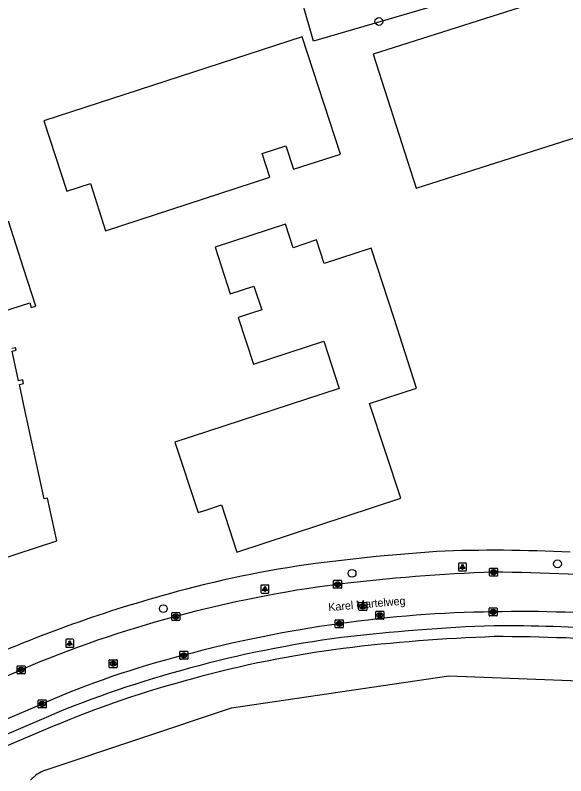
# Model space of a CAD drawing. Extents: x 159503 to 160347, y 382525 to 383272.
# Drawn here: x 159637.5 to 159706.3, y 382704.5 to 382799.5 of the extents above; entities that cross this region are included whole.
import ezdxf

# ---------------------------------------------------------------- set-up
doc = ezdxf.new("R2010")
doc.units = 0
for name, color, linetype in [('IMGEO_Boom', 7, 'Continuous'), ('IMGEO_Groenvoorziening', 7, 'Continuous'), ('IMGEO_Kolk', 7, 'Continuous'), ('IMGEO_Lichtpunt', 7, 'Continuous'), ('IMGEO_Openbare_ruimte_label', 7, 'Continuous'), ('IMGEO_Pand', 7, 'Continuous'), ('IMGEO_Rijbaan_lokaal_open', 7, 'Continuous'), ('IMGEO_Rioolput', 7, 'Continuous'), ('IMGEO_Voetpad_open', 7, 'Continuous')]:
    doc.layers.add(name, color=color, linetype=linetype)

msp = doc.modelspace()

# ---------------------------------------------------------------- linework, layer by layer
at = {"layer": 'IMGEO_Boom'}
for centre in [(159682.989, 382798.739), (159705.309, 382730.985), (159679.639, 382729.808), (159656.051, 382725.396)]:
    msp.add_circle(centre, 0.489, dxfattribs=at)
at = {"layer": 'IMGEO_Groenvoorziening'}
msp.add_lwpolyline([(159742.845, 382815.409), (159730.6, 382811.547), (159707.693, 382805.912), (159674.81, 382796.272), (159673.434, 382801.05)], dxfattribs=at)
at = {"layer": 'IMGEO_Kolk'}
for p, q in [((159696.822, 382729.522), (159696.822, 382730.374)), ((159696.897, 382730.448), (159697.749, 382730.448)), ((159697.823, 382730.374), (159697.823, 382729.522)), ((159697.749, 382729.448), (159696.897, 382729.448)), ((159697.333, 382729.668), (159697.308, 382729.668)), ((159697.31, 382730.228), (159697.335, 382730.228)), ((159677.332, 382728.004), (159677.332, 382728.856)), ((159677.407, 382728.93), (159678.259, 382728.93)), ((159677.82, 382728.71), (159677.845, 382728.71)), ((159678.333, 382728.856), (159678.333, 382728.004)), ((159678.259, 382727.93), (159677.407, 382727.93)), ((159677.843, 382728.15), (159677.818, 382728.15)), ((159657.109, 382723.984), (159657.109, 382724.836)), ((159657.184, 382724.91), (159658.036, 382724.91)), ((159657.597, 382724.69), (159657.622, 382724.69)), ((159658.11, 382724.836), (159658.11, 382723.984)), ((159696.763, 382724.564), (159696.763, 382725.416)), ((159696.838, 382725.49), (159697.69, 382725.49)), ((159697.274, 382724.71), (159697.249, 382724.71)), ((159697.251, 382725.27), (159697.276, 382725.27)), ((159697.764, 382725.416), (159697.764, 382724.564)), ((159658.036, 382723.91), (159657.184, 382723.91)), ((159657.62, 382724.13), (159657.595, 382724.13)), ((159677.544, 382723.076), (159677.544, 382723.928)), ((159677.619, 382724.002), (159678.471, 382724.002)), ((159678.032, 382723.782), (159678.057, 382723.782)), ((159678.545, 382723.928), (159678.545, 382723.076)), ((159697.69, 382724.49), (159696.838, 382724.49)), ((159678.471, 382723.002), (159677.619, 382723.002)), ((159678.055, 382723.222), (159678.03, 382723.222)), ((159658.106, 382719.138), (159658.106, 382719.99)), ((159658.181, 382720.064), (159659.033, 382720.064)), ((159658.594, 382719.844), (159658.619, 382719.844)), ((159659.107, 382719.99), (159659.107, 382719.138)), ((159659.033, 382719.064), (159658.181, 382719.064)), ((159658.617, 382719.284), (159658.592, 382719.284)), ((159637.776, 382717.316), (159637.776, 382718.168)), ((159637.851, 382718.242), (159638.703, 382718.242)), ((159638.264, 382718.022), (159638.289, 382718.022)), ((159638.777, 382718.168), (159638.777, 382717.316)), ((159638.703, 382717.242), (159637.851, 382717.242)), ((159638.287, 382717.462), (159638.262, 382717.462)), ((159640.425, 382713.063), (159640.425, 382713.915)), ((159640.5, 382713.989), (159641.352, 382713.989)), ((159640.936, 382713.209), (159640.911, 382713.209)), ((159640.913, 382713.769), (159640.938, 382713.769)), ((159641.426, 382713.915), (159641.426, 382713.063)), ((159641.352, 382712.989), (159640.5, 382712.989))]:
    msp.add_line(p, q, dxfattribs=at)
for points in [[(159696.822, 382729.522), (159696.822, 382730.374)], [(159696.897, 382730.448), (159697.749, 382730.448)], [(159697.823, 382730.374), (159697.823, 382729.522)], [(159697.749, 382729.448), (159696.897, 382729.448)], [(159697.143, 382730.148), (159697.266, 382730.148), (159697.266, 382729.997), (159697.396, 382730.148), (159697.56, 382730.148), (159697.414, 382729.997), (159697.567, 382729.748), (159697.415, 382729.748), (159697.33, 382729.912), (159697.266, 382729.845), (159697.266, 382729.748), (159697.143, 382729.748), (159697.143, 382730.148)], [(159677.332, 382728.004), (159677.332, 382728.856)], [(159677.407, 382728.93), (159678.259, 382728.93)], [(159677.653, 382728.63), (159677.776, 382728.63), (159677.776, 382728.479), (159677.906, 382728.63), (159678.07, 382728.63), (159677.924, 382728.479), (159678.077, 382728.23), (159677.925, 382728.23), (159677.84, 382728.394), (159677.776, 382728.327), (159677.776, 382728.23), (159677.653, 382728.23), (159677.653, 382728.63)], [(159678.333, 382728.856), (159678.333, 382728.004)], [(159678.259, 382727.93), (159677.407, 382727.93)], [(159657.109, 382723.984), (159657.109, 382724.836)], [(159657.184, 382724.91), (159658.036, 382724.91)], [(159657.43, 382724.61), (159657.553, 382724.61), (159657.553, 382724.459), (159657.683, 382724.61), (159657.847, 382724.61), (159657.701, 382724.459), (159657.854, 382724.21), (159657.702, 382724.21), (159657.617, 382724.374), (159657.553, 382724.307), (159657.553, 382724.21), (159657.43, 382724.21), (159657.43, 382724.61)], [(159658.11, 382724.836), (159658.11, 382723.984)], [(159696.763, 382724.564), (159696.763, 382725.416)], [(159696.838, 382725.49), (159697.69, 382725.49)], [(159697.084, 382725.19), (159697.207, 382725.19), (159697.207, 382725.039), (159697.337, 382725.19), (159697.501, 382725.19), (159697.355, 382725.039), (159697.508, 382724.79), (159697.356, 382724.79), (159697.271, 382724.954), (159697.207, 382724.887), (159697.207, 382724.79), (159697.084, 382724.79), (159697.084, 382725.19)], [(159697.764, 382725.416), (159697.764, 382724.564)], [(159658.036, 382723.91), (159657.184, 382723.91)], [(159677.544, 382723.076), (159677.544, 382723.928)], [(159677.619, 382724.002), (159678.471, 382724.002)], [(159677.865, 382723.702), (159677.988, 382723.702), (159677.988, 382723.551), (159678.118, 382723.702), (159678.282, 382723.702), (159678.136, 382723.551), (159678.289, 382723.302), (159678.137, 382723.302), (159678.052, 382723.466), (159677.988, 382723.399), (159677.988, 382723.302), (159677.865, 382723.302), (159677.865, 382723.702)], [(159678.545, 382723.928), (159678.545, 382723.076)], [(159697.69, 382724.49), (159696.838, 382724.49)], [(159678.471, 382723.002), (159677.619, 382723.002)], [(159658.106, 382719.138), (159658.106, 382719.99)], [(159658.181, 382720.064), (159659.033, 382720.064)], [(159659.107, 382719.99), (159659.107, 382719.138)], [(159659.033, 382719.064), (159658.181, 382719.064)], [(159658.427, 382719.764), (159658.55, 382719.764), (159658.55, 382719.613), (159658.68, 382719.764), (159658.844, 382719.764), (159658.698, 382719.613), (159658.851, 382719.364), (159658.699, 382719.364), (159658.614, 382719.528), (159658.55, 382719.461), (159658.55, 382719.364), (159658.427, 382719.364), (159658.427, 382719.764)], [(159637.776, 382717.316), (159637.776, 382718.168)], [(159637.851, 382718.242), (159638.703, 382718.242)], [(159638.097, 382717.942), (159638.22, 382717.942), (159638.22, 382717.791), (159638.35, 382717.942), (159638.514, 382717.942), (159638.368, 382717.791), (159638.521, 382717.542), (159638.369, 382717.542), (159638.284, 382717.706), (159638.22, 382717.639), (159638.22, 382717.542), (159638.097, 382717.542), (159638.097, 382717.942)], [(159638.777, 382718.168), (159638.777, 382717.316)], [(159638.703, 382717.242), (159637.851, 382717.242)], [(159640.425, 382713.063), (159640.425, 382713.915)], [(159640.5, 382713.989), (159641.352, 382713.989)], [(159640.746, 382713.689), (159640.869, 382713.689), (159640.869, 382713.538), (159640.999, 382713.689), (159641.163, 382713.689), (159641.017, 382713.538), (159641.17, 382713.289), (159641.018, 382713.289), (159640.933, 382713.453), (159640.869, 382713.386), (159640.869, 382713.289), (159640.746, 382713.289), (159640.746, 382713.689)], [(159641.426, 382713.915), (159641.426, 382713.063)], [(159641.352, 382712.989), (159640.5, 382712.989)]]:
    msp.add_lwpolyline(points, dxfattribs=at)
for centre, start, end in [((159696.899, 382730.372), 91.55205, 178.44795), ((159696.899, 382730.372), 91.55205, 178.44795), ((159697.747, 382730.372), 1.55205, 88.44795), ((159697.747, 382730.372), 1.55205, 88.44795), ((159696.899, 382729.524), 181.55205, 268.44795), ((159696.899, 382729.524), 181.55205, 268.44795), ((159697.747, 382729.524), 271.55205, 358.44795), ((159697.747, 382729.524), 271.55205, 358.44795), ((159677.409, 382728.854), 91.55205, 178.44795), ((159677.409, 382728.854), 91.55205, 178.44795), ((159678.257, 382728.854), 1.55205, 88.44795), ((159678.257, 382728.854), 1.55205, 88.44795), ((159677.409, 382728.006), 181.55205, 268.44795), ((159677.409, 382728.006), 181.55205, 268.44795), ((159678.257, 382728.006), 271.55205, 358.44795), ((159678.257, 382728.006), 271.55205, 358.44795), ((159657.186, 382724.834), 91.55205, 178.44795), ((159657.186, 382724.834), 91.55205, 178.44795), ((159658.034, 382724.834), 1.55205, 88.44795), ((159658.034, 382724.834), 1.55205, 88.44795), ((159696.84, 382725.414), 91.55205, 178.44795), ((159696.84, 382725.414), 91.55205, 178.44795), ((159696.84, 382724.566), 181.55205, 268.44795), ((159696.84, 382724.566), 181.55205, 268.44795), ((159697.688, 382725.414), 1.55205, 88.44795), ((159697.688, 382725.414), 1.55205, 88.44795), ((159697.688, 382724.566), 271.55205, 358.44795), ((159697.688, 382724.566), 271.55205, 358.44795), ((159657.186, 382723.986), 181.55205, 268.44795), ((159657.186, 382723.986), 181.55205, 268.44795), ((159658.034, 382723.986), 271.55205, 358.44795), ((159658.034, 382723.986), 271.55205, 358.44795), ((159677.621, 382723.926), 91.55205, 178.44795), ((159677.621, 382723.926), 91.55205, 178.44795), ((159678.469, 382723.926), 1.55205, 88.44795), ((159678.469, 382723.926), 1.55205, 88.44795), ((159677.621, 382723.078), 181.55205, 268.44795), ((159677.621, 382723.078), 181.55205, 268.44795), ((159678.469, 382723.078), 271.55205, 358.44795), ((159678.469, 382723.078), 271.55205, 358.44795), ((159658.183, 382719.988), 91.55205, 178.44795), ((159658.183, 382719.988), 91.55205, 178.44795), ((159659.031, 382719.988), 1.55205, 88.44795), ((159659.031, 382719.988), 1.55205, 88.44795), ((159658.183, 382719.14), 181.55205, 268.44795), ((159658.183, 382719.14), 181.55205, 268.44795), ((159659.031, 382719.14), 271.55205, 358.44795), ((159659.031, 382719.14), 271.55205, 358.44795), ((159637.853, 382718.166), 91.55205, 178.44795), ((159637.853, 382718.166), 91.55205, 178.44795), ((159638.701, 382718.166), 1.55205, 88.44795), ((159638.701, 382718.166), 1.55205, 88.44795), ((159637.853, 382717.318), 181.55205, 268.44795), ((159637.853, 382717.318), 181.55205, 268.44795), ((159638.701, 382717.318), 271.55205, 358.44795), ((159638.701, 382717.318), 271.55205, 358.44795), ((159640.502, 382713.913), 91.55205, 178.44795), ((159640.502, 382713.913), 91.55205, 178.44795), ((159641.35, 382713.913), 1.55205, 88.44795), ((159641.35, 382713.913), 1.55205, 88.44795), ((159640.502, 382713.065), 181.55205, 268.44795), ((159640.502, 382713.065), 181.55205, 268.44795), ((159641.35, 382713.065), 271.55205, 358.44795), ((159641.35, 382713.065), 271.55205, 358.44795)]:
    msp.add_arc(centre, 0.0765, start, end, dxfattribs=at)
for centre, major_axis, ratio, start_param, end_param in [((159697.309, 382729.948), (-0.387, 0.002), 0.722429, 4.712389, 7.853982), ((159697.334, 382729.948), (-0.39, 0.002), 0.717154, 1.570796, 4.712389), ((159677.819, 382728.43), (-0.387, 0.002), 0.722429, 4.712389, 7.853982), ((159677.844, 382728.43), (-0.39, 0.002), 0.717154, 1.570796, 4.712389), ((159657.596, 382724.41), (-0.387, 0.002), 0.722429, 4.712389, 7.853982), ((159657.621, 382724.41), (-0.39, 0.002), 0.717154, 1.570796, 4.712389), ((159697.25, 382724.99), (-0.387, 0.002), 0.722429, 4.712389, 7.853982), ((159697.275, 382724.99), (-0.39, 0.002), 0.717154, 1.570796, 4.712389), ((159678.031, 382723.502), (-0.387, 0.002), 0.722429, 4.712389, 7.853982), ((159678.056, 382723.502), (-0.39, 0.002), 0.717154, 1.570796, 4.712389), ((159658.593, 382719.564), (-0.387, 0.002), 0.722429, 4.712389, 7.853982), ((159658.618, 382719.564), (-0.39, 0.002), 0.717154, 1.570796, 4.712389), ((159638.263, 382717.742), (-0.387, 0.002), 0.722429, 4.712389, 7.853982), ((159638.288, 382717.742), (-0.39, 0.002), 0.717154, 1.570796, 4.712389), ((159640.912, 382713.489), (-0.387, 0.002), 0.722429, 4.712389, 7.853982), ((159640.937, 382713.489), (-0.39, 0.002), 0.717154, 1.570796, 4.712389)]:
    msp.add_ellipse(centre, major_axis=major_axis, ratio=ratio, start_param=start_param, end_param=end_param, dxfattribs=at)
at = {"layer": 'IMGEO_Lichtpunt'}
for p, q in [((159692.934, 382730.998), (159692.934, 382730.191)), ((159692.934, 382730.998), (159692.934, 382730.191)), ((159693.836, 382731.093), (159693.028, 382731.093)), ((159693.836, 382731.093), (159693.028, 382731.093)), ((159693.93, 382730.191), (159693.93, 382730.998)), ((159693.93, 382730.191), (159693.93, 382730.998)), ((159693.028, 382730.097), (159693.836, 382730.097)), ((159693.028, 382730.097), (159693.836, 382730.097)), ((159668.256, 382728.242), (159668.256, 382727.435)), ((159668.256, 382728.242), (159668.256, 382727.435)), ((159669.158, 382728.337), (159668.35, 382728.337)), ((159669.158, 382728.337), (159668.35, 382728.337)), ((159669.252, 382727.435), (159669.252, 382728.242)), ((159669.252, 382727.435), (159669.252, 382728.242)), ((159668.35, 382727.341), (159669.158, 382727.341)), ((159668.35, 382727.341), (159669.158, 382727.341)), ((159643.86, 382721.465), (159643.86, 382720.658)), ((159643.86, 382721.465), (159643.86, 382720.658)), ((159644.762, 382721.56), (159643.954, 382721.56)), ((159644.762, 382721.56), (159643.954, 382721.56)), ((159644.856, 382720.658), (159644.856, 382721.465)), ((159644.856, 382720.658), (159644.856, 382721.465)), ((159643.954, 382720.564), (159644.762, 382720.564)), ((159643.954, 382720.564), (159644.762, 382720.564))]:
    msp.add_line(p, q, dxfattribs=at)
for points in [[(159693.308, 382730.662), (159693.347, 382730.634), (159693.159, 382730.372), (159693.121, 382730.399), (159693.308, 382730.662)], [(159693.41, 382730.614), (159693.457, 382730.614), (159693.457, 382730.292), (159693.41, 382730.292), (159693.41, 382730.614)], [(159693.52, 382730.634), (159693.558, 382730.661), (159693.745, 382730.399), (159693.706, 382730.371), (159693.52, 382730.634)], [(159668.63, 382727.906), (159668.669, 382727.878), (159668.481, 382727.616), (159668.443, 382727.643), (159668.63, 382727.906)], [(159668.732, 382727.858), (159668.779, 382727.858), (159668.779, 382727.536), (159668.732, 382727.536), (159668.732, 382727.858)], [(159668.842, 382727.878), (159668.88, 382727.905), (159669.067, 382727.643), (159669.028, 382727.615), (159668.842, 382727.878)], [(159644.234, 382721.129), (159644.273, 382721.101), (159644.085, 382720.839), (159644.047, 382720.866), (159644.234, 382721.129)], [(159644.336, 382721.081), (159644.383, 382721.081), (159644.383, 382720.759), (159644.336, 382720.759), (159644.336, 382721.081)], [(159644.446, 382721.101), (159644.484, 382721.128), (159644.671, 382720.866), (159644.632, 382720.838), (159644.446, 382721.101)]]:
    msp.add_lwpolyline(points, dxfattribs=at)
for centre in [(159693.433, 382730.796), (159668.755, 382728.04), (159644.359, 382721.263)]:
    msp.add_circle(centre, 0.0994, dxfattribs=at)
for centre, start, end in [((159693.028, 382730.998), 90, 180), ((159693.028, 382730.998), 90, 180), ((159693.836, 382730.998), 0, 90), ((159693.836, 382730.998), 0, 90), ((159693.028, 382730.191), 180, 270), ((159693.028, 382730.191), 180, 270), ((159693.836, 382730.191), 270, 0), ((159693.836, 382730.191), 270, 360), ((159668.35, 382728.242), 90, 180), ((159668.35, 382728.242), 90, 180), ((159668.35, 382727.435), 180, 270), ((159668.35, 382727.435), 180, 270), ((159669.158, 382728.242), 0, 90), ((159669.158, 382728.242), 0, 90), ((159669.158, 382727.435), 270, 0), ((159669.158, 382727.435), 270, 360), ((159643.954, 382721.465), 90, 180), ((159643.954, 382721.465), 90, 180), ((159644.762, 382721.465), 0, 90), ((159644.762, 382721.465), 0, 90), ((159643.954, 382720.658), 180, 270), ((159643.954, 382720.658), 180, 270), ((159644.762, 382720.658), 270, 0), ((159644.762, 382720.658), 270, 360)]:
    msp.add_arc(centre, 0.0946, start, end, dxfattribs=at)
at = {"layer": 'IMGEO_Pand'}
for points in [[(159705.767, 382802.152), (159682.294, 382794.673), (159687.633, 382777.914), (159713.049, 382786.012), (159722.358, 382756.794), (159722.657, 382756.889), (159723.605, 382753.912), (159720.541, 382752.936), (159721.48, 382750), (159722.471, 382746.901), (159723.999, 382742.131), (159724.396, 382740.892), (159752.918, 382750), (159753.541, 382750.199), (159749.635, 382762.458), (159747.561, 382761.797), (159745.396, 382768.592), (159738.73, 382766.468), (159735.002, 382765.28), (159731.853, 382775.164), (159733.127, 382775.57), (159726.63, 382795.959)], [(159673.384, 382796.837), (159641.142, 382786.337), (159644.013, 382777.531), (159646.935, 382778.494), (159648.834, 382772.604), (159669.369, 382779.311), (159668.397, 382782.238), (159671.375, 382783.21), (159672.33, 382780.28), (159678.18, 382782.18), (159673.384, 382796.837)], [(159635.888, 382762.477), (159639.355, 382763.579), (159639.54, 382762.997), (159640.111, 382763.179), (159638.587, 382767.942), (159636.711, 382773.808)], [(159681.815, 382751.023), (159687.697, 382752.922), (159684.881, 382761.646), (159682.02, 382770.428), (159676.161, 382768.5), (159675.209, 382771.449), (159672.267, 382770.481), (159671.303, 382773.418), (159662.523, 382770.552), (159664.417, 382764.699), (159667.364, 382765.67), (159668.349, 382762.731), (159665.398, 382761.756), (159667.31, 382755.914), (159676.106, 382758.788), (159678.029, 382752.88), (159657.503, 382746.17), (159660.423, 382737.392), (159661.358, 382737.709), (159663.316, 382738.364), (159665.238, 382732.431), (159685.741, 382739.181), (159681.815, 382751.023)], [(159625.037, 382728.065), (159642.741, 382733.862), (159641.591, 382739.183), (159641.168, 382739.092), (159638.804, 382750), (159638.069, 382753.392), (159638.582, 382753.503), (159638.48, 382753.973), (159637.963, 382753.86), (159637.162, 382757.556), (159637.668, 382757.666), (159637.599, 382757.984), (159637.108, 382757.877)], [(159641.27, 382705.207), (159664.57, 382713.021), (159691.74, 382716.986), (159715.697, 382716.063)]]:
    msp.add_lwpolyline(points, dxfattribs=at)
msp.add_arc((159642.683, 382701.29), 4.164, 109.83892, 140.35503, dxfattribs=at)
at = {"layer": 'IMGEO_Rijbaan_lokaal_open'}
for points in [[(159623.68, 382711.468), (159624.794, 382711.953), (159638.277, 382717.741)], [(159624.664, 382706.553), (159626.254, 382707.24), (159640.926, 382713.49)]]:
    msp.add_lwpolyline(points, dxfattribs=at)
for centre, radius, start, end in [((159705.491, 382499.343), 230.749, 92.02869, 96.88426), ((159693.353, 382379.227), 350.742, 86.30914, 89.35141), ((159697.26, 382577.785), 151.89, 97.34835, 105.132), ((159699.017, 382577.567), 147.434, 90.68145, 98.17842), ((159700.776, 382560.643), 164.385, 84.95233, 91.22406), ((159692.261, 382592.582), 136.305, 104.72718, 113.3317), ((159698.899, 382570.59), 154.328, 97.76654, 105.13436), ((159685.275, 382613.183), 109.673, 104.07275, 113.85158)]:
    msp.add_arc(centre, radius, start, end, dxfattribs=at)
at = {"layer": 'IMGEO_Rioolput'}
for p, q in [((159680.491, 382725.238), (159680.491, 382726.09)), ((159680.566, 382726.164), (159681.418, 382726.164)), ((159680.979, 382725.944), (159681.004, 382725.944)), ((159681.492, 382726.09), (159681.492, 382725.238)), ((159681.418, 382725.164), (159680.566, 382725.164)), ((159681.002, 382725.384), (159680.977, 382725.384)), ((159682.608, 382724.15), (159682.608, 382725.002)), ((159682.683, 382725.076), (159683.535, 382725.076)), ((159683.096, 382724.856), (159683.121, 382724.856)), ((159683.609, 382725.002), (159683.609, 382724.15)), ((159683.535, 382724.076), (159682.683, 382724.076)), ((159683.119, 382724.296), (159683.094, 382724.296)), ((159649.287, 382718.091), (159649.287, 382718.943)), ((159649.362, 382719.017), (159650.214, 382719.017)), ((159650.288, 382718.943), (159650.288, 382718.091)), ((159650.214, 382718.017), (159649.362, 382718.017)), ((159649.798, 382718.237), (159649.773, 382718.237)), ((159649.775, 382718.797), (159649.8, 382718.797))]:
    msp.add_line(p, q, dxfattribs=at)
for points in [[(159680.491, 382725.238), (159680.491, 382726.09)], [(159680.566, 382726.164), (159681.418, 382726.164)], [(159681.08, 382725.862), (159680.828, 382725.864), (159680.828, 382725.464)], [(159680.828, 382725.464), (159680.952, 382725.464), (159680.952, 382725.626), (159680.963, 382725.626)], [(159681.006, 382725.783), (159680.952, 382725.783), (159680.952, 382725.702)], [(159680.952, 382725.702), (159681.004, 382725.702)], [(159681.01, 382725.597), (159681.081, 382725.464), (159681.221, 382725.464), (159681.156, 382725.59)], [(159681.492, 382726.09), (159681.492, 382725.238)], [(159681.418, 382725.164), (159680.566, 382725.164)], [(159682.608, 382724.15), (159682.608, 382725.002)], [(159682.683, 382725.076), (159683.535, 382725.076)], [(159683.197, 382724.774), (159682.945, 382724.776), (159682.945, 382724.376)], [(159683.123, 382724.695), (159683.069, 382724.695), (159683.069, 382724.614)], [(159683.069, 382724.614), (159683.121, 382724.614)], [(159683.609, 382725.002), (159683.609, 382724.15)], [(159683.535, 382724.076), (159682.683, 382724.076)], [(159682.945, 382724.376), (159683.069, 382724.376), (159683.069, 382724.538), (159683.08, 382724.538)], [(159683.127, 382724.509), (159683.198, 382724.376), (159683.338, 382724.376), (159683.273, 382724.502)], [(159649.287, 382718.091), (159649.287, 382718.943)], [(159649.362, 382719.017), (159650.214, 382719.017)], [(159650.288, 382718.943), (159650.288, 382718.091)], [(159650.214, 382718.017), (159649.362, 382718.017)], [(159649.876, 382718.715), (159649.624, 382718.717), (159649.624, 382718.317)], [(159649.624, 382718.317), (159649.748, 382718.317), (159649.748, 382718.479), (159649.759, 382718.479)], [(159649.802, 382718.636), (159649.748, 382718.636), (159649.748, 382718.555)], [(159649.748, 382718.555), (159649.8, 382718.555)], [(159649.806, 382718.45), (159649.877, 382718.317), (159650.017, 382718.317), (159649.952, 382718.443)]]:
    msp.add_lwpolyline(points, dxfattribs=at)
for centre, radius, start, end in [((159680.568, 382726.088), 0.0765, 91.55205, 178.44795), ((159680.568, 382726.088), 0.0765, 91.55205, 178.44795), ((159680.962, 382725.573), 0.0533, 26.02933, 88.69889), ((159680.988, 382725.891), 0.19, 274.7715, 282.96867), ((159681.012, 382725.687), 0.0964, 77.00612, 93.18647), ((159681.026, 382725.744), 0.0378, 276.66336, 79.67722), ((159681.079, 382725.752), 0.109, 350.36119, 89.41601), ((159681.077, 382725.752), 0.112, 277.58423, 350.98172), ((159681.061, 382725.537), 0.108, 29.51342, 73.79051), ((159681.416, 382726.088), 0.0765, 1.55205, 88.44795), ((159681.416, 382726.088), 0.0765, 1.55205, 88.44795), ((159680.568, 382725.24), 0.0765, 181.55205, 268.44795), ((159680.568, 382725.24), 0.0765, 181.55205, 268.44795), ((159681.416, 382725.24), 0.0765, 271.55205, 358.44795), ((159681.416, 382725.24), 0.0765, 271.55205, 358.44795), ((159682.685, 382725), 0.0765, 91.55205, 178.44795), ((159682.685, 382725), 0.0765, 91.55205, 178.44795), ((159683.105, 382724.803), 0.19, 274.7715, 282.96867), ((159683.129, 382724.599), 0.0964, 77.00612, 93.18647), ((159683.143, 382724.656), 0.0378, 276.66336, 79.67722), ((159683.196, 382724.664), 0.109, 350.36119, 89.41601), ((159683.194, 382724.664), 0.112, 277.58423, 350.98172), ((159683.178, 382724.449), 0.108, 29.51342, 73.79051), ((159683.533, 382725), 0.0765, 1.55205, 88.44795), ((159683.533, 382725), 0.0765, 1.55205, 88.44795), ((159682.685, 382724.152), 0.0765, 181.55205, 268.44795), ((159682.685, 382724.152), 0.0765, 181.55205, 268.44795), ((159683.079, 382724.485), 0.0533, 26.02933, 88.69889), ((159683.533, 382724.152), 0.0765, 271.55205, 358.44795), ((159683.533, 382724.152), 0.0765, 271.55205, 358.44795), ((159649.364, 382718.941), 0.0765, 91.55205, 178.44795), ((159649.364, 382718.941), 0.0765, 91.55205, 178.44795), ((159650.212, 382718.941), 0.0765, 1.55205, 88.44795), ((159650.212, 382718.941), 0.0765, 1.55205, 88.44795), ((159649.364, 382718.093), 0.0765, 181.55205, 268.44795), ((159649.364, 382718.093), 0.0765, 181.55205, 268.44795), ((159649.758, 382718.426), 0.0533, 26.02933, 88.69889), ((159649.784, 382718.744), 0.19, 274.7715, 282.96867), ((159649.808, 382718.54), 0.0964, 77.00612, 93.18647), ((159649.822, 382718.597), 0.0378, 276.66336, 79.67722), ((159649.875, 382718.605), 0.109, 350.36119, 89.41601), ((159649.873, 382718.605), 0.112, 277.58423, 350.98172), ((159649.857, 382718.39), 0.108, 29.51342, 73.79051), ((159650.212, 382718.093), 0.0765, 271.55205, 358.44795), ((159650.212, 382718.093), 0.0765, 271.55205, 358.44795)]:
    msp.add_arc(centre, radius, start, end, dxfattribs=at)
for centre, major_axis, ratio, start_param, end_param in [((159680.978, 382725.664), (-0.387, 0.002), 0.722429, 4.712389, 7.853982), ((159681.003, 382725.664), (-0.39, 0.002), 0.717154, 1.570796, 4.712389), ((159683.095, 382724.576), (-0.387, 0.002), 0.722429, 4.712389, 7.853982), ((159683.12, 382724.576), (-0.39, 0.002), 0.717154, 1.570796, 4.712389), ((159649.774, 382718.517), (-0.387, 0.002), 0.722429, 4.712389, 7.853982), ((159649.799, 382718.517), (-0.39, 0.002), 0.717154, 1.570796, 4.712389)]:
    msp.add_ellipse(centre, major_axis=major_axis, ratio=ratio, start_param=start_param, end_param=end_param, dxfattribs=at)
at = {"layer": 'IMGEO_Voetpad_open'}
for points in [[(159690.236, 382732.536), (159682.644, 382731.888), (159675.074, 382731.025)], [(159641.687, 382711.932), (159628.035, 382706.081)], [(159642.215, 382710.655), (159635.428, 382707.808)]]:
    msp.add_lwpolyline(points, dxfattribs=at)
for centre, radius, start, end in [((159697.488, 382555.269), 177.415, 86.96245, 92.34256), ((159693.42, 382596.018), 136.248, 97.73847, 105.65117), ((159701.272, 382565.217), 168.027, 105.39586, 114.51133), ((159706.243, 382487.021), 236.406, 92.14832, 96.786), ((159697.786, 382501.576), 221.685, 86.27886, 90.1048), ((159696.794, 382580.988), 141.992, 97.48028, 105.29974), ((159705.287, 382500.203), 221.831, 92.03487, 96.93268), ((159697.556, 382491.794), 230.1, 85.58418, 90.03625), ((159696.201, 382584.04), 137.515, 97.39088, 105.38605), ((159694.437, 382586.106), 136.436, 104.91228, 112.74508), ((159693.098, 382590.157), 130.801, 104.78647, 112.89281)]:
    msp.add_arc(centre, radius, start, end, dxfattribs=at)

# ---------------------------------------------------------------- texts
at = {"layer": 'IMGEO_Openbare_ruimte_label'}
msp.add_text('Karel Martelweg', height=1, rotation=4.99208, dxfattribs=at).set_placement((159676.712, 382725.067))

doc.saveas('drawing.dxf')
